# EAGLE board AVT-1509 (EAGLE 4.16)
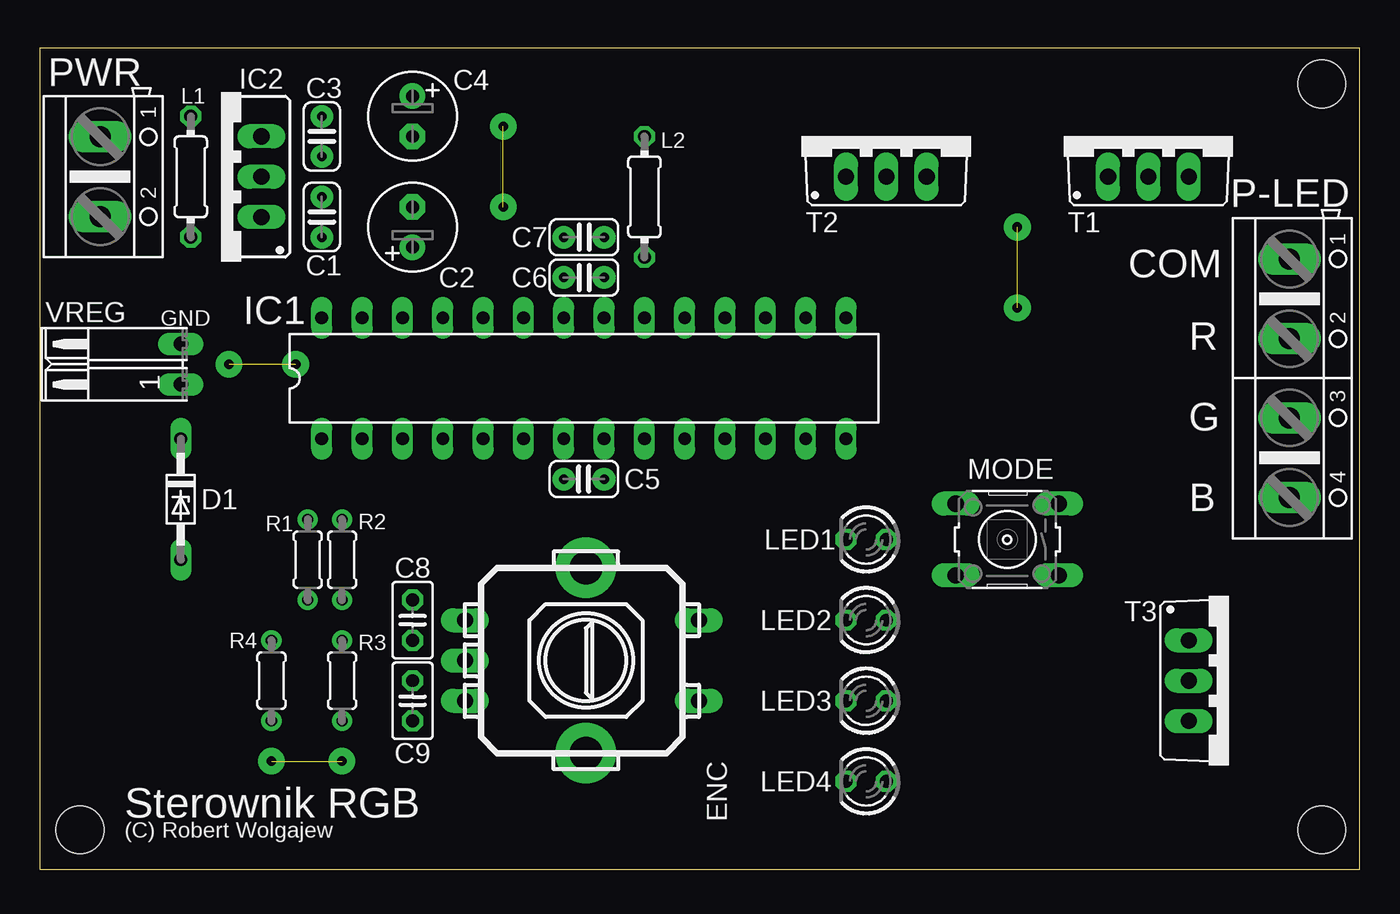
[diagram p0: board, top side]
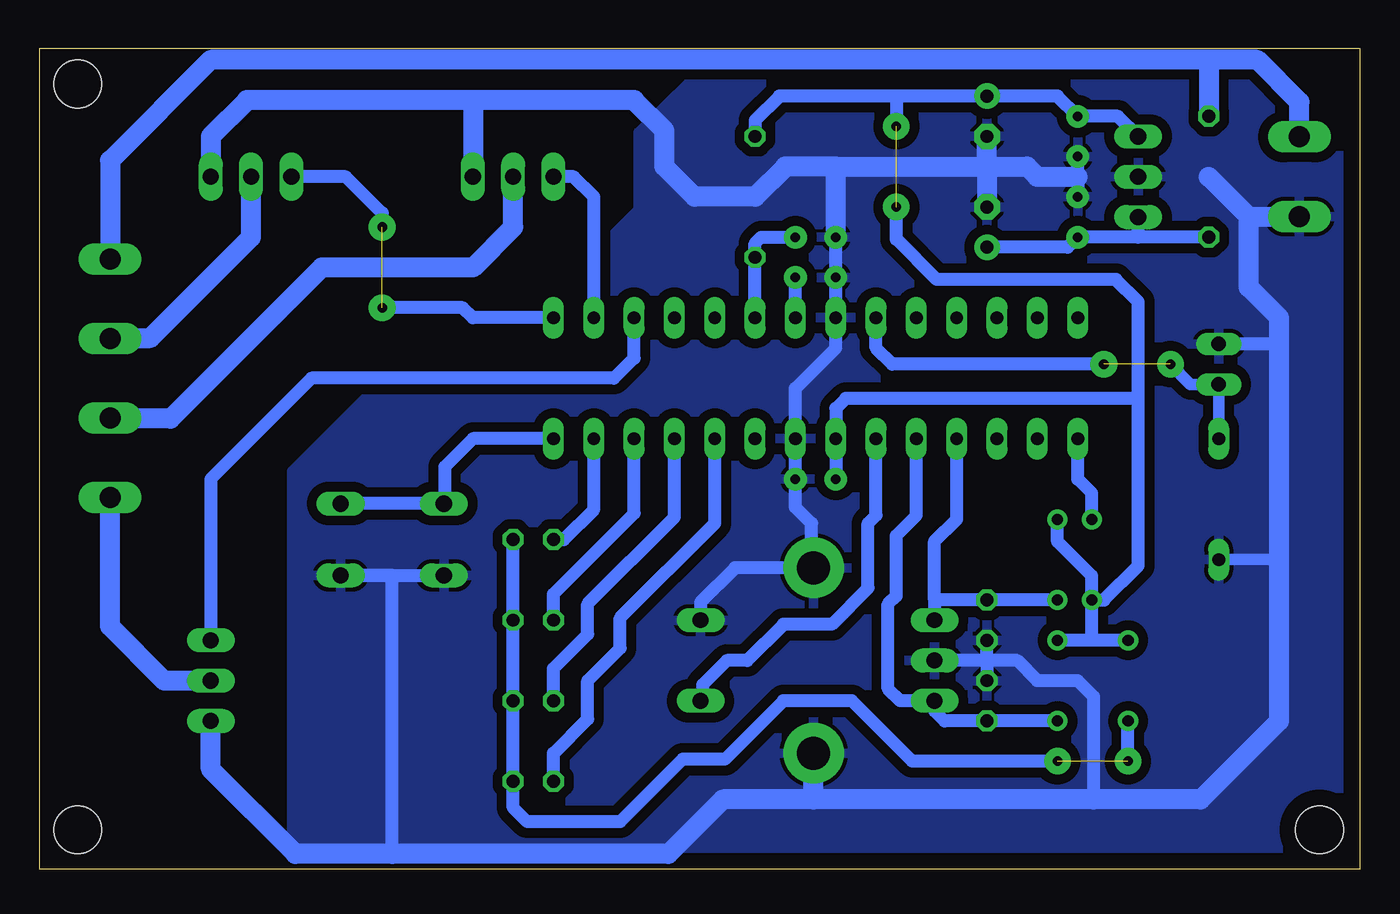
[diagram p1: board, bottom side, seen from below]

Size 83.17 x 51.74 mm. Coordinates in mm from the lower left corner, seen from the top.
Outline: 0,0 83.17,0 83.17,51.74 0,51.74 0,0
Copper layers (1*16): Top 0.035mm / dielectric 1.5mm / Bottom 0.035mm
Design rules "default": minimum track width 10mil, minimum drill 24mil, track to track 8mil, track to pad 8mil, pad to pad 8mil, via to via 8mil, smd to smd 8mil, copper to edge 40mil, drill to drill 8mil, minimum pad ring 10mil, minimum via ring 8mil, stop-mask expansion 4mil, vias tented up to drill 0mil, thermal gap 10mil
Holes 3 mm at 2.54,2.5 80.77,2.5 80.77,49.49

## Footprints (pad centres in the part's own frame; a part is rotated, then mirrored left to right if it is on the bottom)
C025-024X044 = drill 0.6 pad 1.422 round: 1 -1.27,0; 2 1.27,0
E2,5-6 = drill 0.813 pad 1.6 round: + -1.27,0 | drill 0.813 pad 1.6 octagon: - 1.27,0
C025-025X050 = drill 0.813 octagon: 1 -1.27,0; 2 1.27,0
DO34Z7 = drill 0.813 long: A 3.81,0; C -3.81,0
ENCODER = drill 1 long: A -2.54,0; B 2.54,0; C 0,0; D -2.54,14.732; E 2.54,14.732 | drill 2.083 pad 3.81 round: CHS1 -5.842,7.62; CHS2 5.842,7.62
DIL28-3 = drill 0.813 long: 1 -16.51,-3.81; 2 -13.97,-3.81; 3 -11.43,-3.81; 4 -8.89,-3.81; 5 -6.35,-3.81; 6 -3.81,-3.81; 7 -1.27,-3.81; 8 1.27,-3.81; 9 3.81,-3.81; 10 6.35,-3.81; 11 8.89,-3.81; 12 11.43,-3.81; 13 13.97,-3.81; 14 16.51,-3.81; 15 16.51,3.81; 16 13.97,3.81; 17 11.43,3.81; 18 8.89,3.81; 19 6.35,3.81; 20 3.81,3.81; 21 1.27,3.81; 22 -1.27,3.81; 23 -3.81,3.81; 24 -6.35,3.81; 25 -8.89,3.81; 26 -11.43,3.81; 27 -13.97,3.81; 28 -16.51,3.81
78XXS = drill 1.016 long: GND 0,-2.54; IN -2.54,-2.54; OUT 2.54,-2.54
0204/7 = drill 0.813 octagon: 1 -3.81,0; 2 3.81,0
LED3MM = drill 0.813 octagon: A -1.27,0; K 1.27,0
B3F-10XX = drill 1.016 long: 1 -3.251,2.261; 2 3.251,2.261; 3 -3.251,-2.261; 4 3.251,-2.261
AK500/4 = drill 1.321 long: 1 -7.518,0; 2 -2.489,0; 3 2.489,0; 4 7.518,0
AK500/2 = drill 1.321 long: 1 -2.515,0; 2 2.515,0
0204/5 = drill 0.7 pad 1.27 round: 1 -2.54,0; 2 2.54,0
TO220BV = drill 1.016 long: D 0,-2.54; G -2.54,-2.54; S 2.54,-2.54
02PA = drill 0.914 long: 1 -1.27,0; 2 1.27,0

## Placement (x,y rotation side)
C1  100nF  [C025-024X044]  17.77,41.11 90 top
C2  220uF  [E2,5-6]  23.49,40.48 90 top
C3  100nF  [C025-024X044]  17.77,46.19 270 top
C4  100uF  [E2,5-6]  23.49,47.46 270 top
C5  100nF  [C025-024X044]  34.28,24.6 180 top
C6  100nF  [C025-024X044]  34.28,37.3 0 top
C7  100nF  [C025-024X044]  34.28,39.84 0 top
C8  100nF  [C025-025X050]  23.49,15.71 270 top
C9  100nF  [C025-025X050]  23.49,10.63 90 top
D1  5V1  [DO34Z7]  8.88,23.33 270 top
ENC  [ENCODER]  26.79,13.17 270 top
IC1  Atmega8  [DIL28-3]  34.28,30.95 0 top
IC2  7805  [78XXS]  11.42,43.65 90 top
L1  100uH  [0204/7]  9.52,43.65 270 top
L2  10uH  [0204/7]  38.09,42.38 270 top
LED1  [LED3MM]  52.07,20.79 180 top
LED2  [LED3MM]  52.07,15.71 180 top
LED3  [LED3MM]  52.07,10.63 180 top
LED4  [LED3MM]  52.07,5.55 180 top
MODE  [B3F-10XX]  60.96,20.79 180 top
P-LED  [AK500/4]  78.73,30.95 270 top
PWR  [AK500/2]  3.81,43.65 270 top
R1  22K  [0204/5]  16.89,19.52 90 top
R2  1K  [0204/5]  19.05,19.52 90 top
R3  1K  [0204/5]  19.05,11.9 90 top
R4  220  [0204/5]  14.6,11.9 90 top
T1  BUZ11  [TO220BV]  69.84,46.19 0 top
T2  BUZ11  [TO220BV]  53.34,46.19 0 top
T3  BUZ11  [TO220BV]  74.93,11.9 270 top
VREG  [02PA]  8.88,31.84 90 top

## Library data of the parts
C1-C9 L1 L2 R1-R4 = rcl
D1 = diode
ENC = RW_Encoder
IC1 = atmel
IC2 = v-reg
LED1-LED4 = led
MODE = switch-omron
P-LED PWR = con-ptr500
T1-T3 = transistor-power
VREG = con-amp-quick

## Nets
+5V: C3.1 C4.+ C5.2 IC1.7 IC2.OUT L2.1 R1.1 R2.2 R3.2 R4.2
GND: C1.2 C2.- C3.2 C4.- C5.1 C6.1 C7.1 C8.2 C9.2 D1.A ENC.C ENC.CHS1 ENC.CHS2 ENC.D IC1.8 IC1.22 IC2.GND MODE.1 MODE.2 PWR.2 T1.S T2.S T3.S VREG.2
N$1: C7.2 IC1.20 L2.2
N$2: C6.2 IC1.21
N$4: IC1.1 R1.2
N$5: ENC.E IC1.6
N$6: IC1.14 MODE.3 MODE.4
N$7: IC1.10 LED4.K
N$8: IC1.11 LED3.K
N$9: IC1.12 LED2.K
N$10: IC1.13 LED1.K
N$11: LED1.A LED2.A LED3.A LED4.A R4.1
N$12: IC1.17 T3.G
N$13: IC1.16 T2.G
N$14: IC1.15 T1.G
N$15: P-LED.4 T3.D
N$16: P-LED.3 T2.D
N$17: L1.1 P-LED.1 PWR.1
N$18: P-LED.2 T1.D
N$19: D1.C IC1.23 VREG.1
N$68: C8.1 ENC.A IC1.4 R2.1
N$77: C1.1 C2.+ IC2.IN L1.2
N$88: C9.1 ENC.B IC1.5 R3.1

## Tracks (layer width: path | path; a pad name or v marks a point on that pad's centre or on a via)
+5V  (via drill 0.6 pad 1.68)  (1 unrouted)
  Bottom 0.813: C5.2 IC1.7 33.02,29.05 32.38,29.68 13.97,29.68 | 29.2,48.73 C4.+ 19.05,48.73 C3.1 15.24,47.46 IC2.OUT | 29.2,48.73 v29.2,46.83 | 29.2,48.73 36.57,48.73 38.09,47.21 L2.1 | v29.2,41.75 29.2,39.71 26.66,37.17 15.36,37.17 13.97,35.78 13.97,29.68 | R4.2 16.89,14.44 | 16.89,14.44 R3.2 | 16.89,14.44 R1.1 | R1.1 16.89,18.5 19.05,20.66 R2.2 | 13.97,29.68 13.97,19.14 16.12,16.98 R1.1
GND
  Bottom 0.737: 5.08,19.52 D1.A
  Bottom 0.813: C3.2 17.77,43.65 C1.2 | C2.- 23.49,43.65 | 23.49,13.17 C8.2 | C7.1 C6.1 IC1.22 33.02,32.86 35.55,30.32 IC1.8 C5.1 35.55,22.82 34.54,21.81 34.54,19.01 | 23.49,13.17 C9.2 | 57.68,18.53 MODE.2 | 57.68,18.53 MODE.1 60.98,18.53 60.96,18.5 60.96,0.98 | 57.68,18.53 57.65,18.5 | 16.76,4.41 16.76,10.88 17.77,11.9 20.31,11.9 21.59,13.17 23.49,13.17 | 5.08,33.11 VREG.2 | 23.49,13.17 ENC.C | ENC.D 41.52,16.85 39.37,19.01 34.54,19.01 | ENC.CHS1 34.54,19.01
  Bottom 1.27: 23.49,44.29 C2.- | 23.49,44.29 C4.- | 7.01,41.13 PWR.2 | 7.01,41.13 9.52,43.65 | 17.77,43.65 20.31,43.65 20.95,44.29 23.49,44.29 | 55.87,48.48 70.1,48.48 72.39,46.19 T1.S | 55.87,48.48 T2.S | 33.02,44.29 23.49,44.29 | 33.02,44.29 36.19,44.29 38.09,42.38 41.91,42.38 43.81,44.29 43.81,46.57 45.71,48.48 55.87,48.48 | C7.1 33.02,44.29 | 7.01,41.13 7.01,36.69 5.08,34.76 5.08,33.11 5.08,19.52 5.08,9.36 10.03,4.41 16.76,4.41 34.41,4.41 | 34.41,4.41 34.41,4.4 | 34.41,4.41 40.13,4.41 43.56,0.98 60.96,0.98 67.05,0.98 72.39,6.31 T3.S | 34.41,4.41 ENC.CHS2
  pour Bottom (isolate 0.61): 0.5,51.27 40.63,51.27 45.46,46.44 45.46,41.62 48.51,38.57 53.84,38.57 67.31,25.11 67.31,0.72 0.5,0.72
N$1
  Bottom 0.813: IC1.20 L2.2 38.09,39.46 37.71,39.84 C7.2
N$2
  Bottom 0.813: IC1.21 C6.2
N$4
  Bottom 0.813: R1.2 16.89,23.71 17.77,24.6 IC1.1
N$5
  Bottom 0.813: IC1.6 30.48,22.31 30.98,21.81 30.98,17.74 33.27,15.46 36.32,15.46 38.6,13.17 39.87,13.17 41.4,11.65 41.4,10.63 ENC.E
N$6
  Bottom 0.813: IC1.14 55.87,27.14 57.65,25.36 57.65,23.08 57.68,23.05 MODE.4 64.23,23.05 | 64.23,23.05 MODE.3 | 64.23,23.05 64.26,23.08
N$7
  Bottom 0.813: IC1.10 40.63,21.81 46.6,15.84 46.6,13.93 48.64,11.9 48.64,9.49 50.79,7.33 LED4.K
N$8
  Bottom 0.813: IC1.11 43.17,22.19 48.64,16.73 48.64,14.82 50.79,12.66 LED3.K
N$9
  Bottom 0.813: IC1.12 45.71,22.44 50.79,17.36 LED2.K
N$10
  Bottom 0.813: IC1.13 48.25,22.7 50.16,20.79 LED1.K
N$11  (via drill 0.6 pad 1.68)  (1 unrouted)
  Bottom 0.813: LED1.A LED2.A LED3.A LED4.A 53.34,3.9 52.45,3.01 46.6,3.01 42.67,6.95 40,6.95 36.32,10.63 32,10.63 28.19,6.82 v19.05,6.82 | v14.6,6.82 R4.1
N$12
  Bottom 0.813: IC1.17 45.71,32.22 46.98,30.95 66.04,30.95 72.39,24.6 T3.G
N$13
  Bottom 0.813: IC1.16 48.25,42.38 49.52,43.65 T2.G
N$14  (via drill 0.6 pad 1.68)  (1 unrouted)
  Bottom 0.813: T1.G 63.88,43.65 61.59,41.36 v61.59,40.48 | IC1.15 55.87,34.76 56.51,35.4 v61.59,35.4
N$15
  Bottom 1.27: T3.D 75.31,11.9 78.73,15.33 P-LED.4 78.73,23.46
N$16
  Bottom 1.27: T2.D 53.34,40.48 55.87,37.94 65.4,37.94 74.93,28.41 78.73,28.41 P-LED.3
N$17
  Bottom 1.27: P-LED.1 78.73,44.67 72.39,51.02 9.52,51.02 | 9.52,51.02 6.47,51.02 3.81,48.35 PWR.1 3.81,46.06 | 9.52,51.02 L1.1
N$18
  Bottom 1.27: T1.D 69.84,39.84 76.2,33.49 78.73,33.49 P-LED.2
N$19  (via drill 0.6 pad 1.68)  (1 unrouted)
  Bottom 0.737: D1.C VREG.1 10.66,30.57 v11.93,31.84
  Bottom 0.813: IC1.23 30.48,32.86 29.46,31.84 v16.12,31.84
N$68
  Bottom 0.813: 26.78,16.98 26.78,20.67 25.39,22.06 IC1.4 | 26.78,16.98 C8.1 R2.1 | 26.78,16.98 26.79,16.98 ENC.A
N$77
  Bottom 0.813: L1.2 13.97,39.84 | 13.97,39.84 C1.1 18.41,39.2 C2.+ | 13.97,39.84 IC2.IN
N$88
  Bottom 0.813: R3.1 C9.1 26.16,9.36 26.79,9.99 ENC.B | ENC.B | IC1.5 27.93,22.31 29.2,21.04 29.2,17.23 29.71,16.73 29.71,11.39 28.95,10.63 ENC.B | ENC.B 26.66,10.63

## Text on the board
tNames: COM | GND | R | G | B | Sterownik RGB | (C) Robert Wolgajew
